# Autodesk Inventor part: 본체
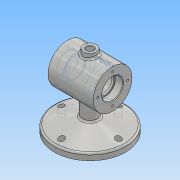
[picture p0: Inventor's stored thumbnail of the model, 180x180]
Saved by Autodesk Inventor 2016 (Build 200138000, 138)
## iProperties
Created: 2018-12
Part Number: 본체
Material: 알루미늄 6061
Document SubType Name: Modeling
Designer: Administrator
Density: 2.7 g/cm^3
Appearance: 알루미늄 - 평지
Author: Administrator
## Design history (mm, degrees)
sketch "스케치2"
  geometry: L1 (0, 0)-(70, 0); L2 (70, 0)-(70, 30); L3 (70, 30)-(0, 30); L4 (0, 30)-(0, 0); L5 (0, 16)-(12, 16); L6 (12, 16)-(12, 14); L7 (12, 14)-(15, 14); L8 (15, 14)-(15, 25); L9 (15, 25)-(55, 25); L10 (55, 25)-(55, 14); L11 (55, 14)-(58, 14); L12 (58, 14)-(58, 16); L13 (58, 16)-(70, 16)
  constraints: 26 end point, 7 perpendicular, 6 point on line, 2 horizontal, 2 parallel
  dimensions: "d0" = 70 distance between parallel lines of L2 L4; "d1" = 32 diameter of L5 L1; "d2" = 28 diameter of L7 L1; "d3" = 3 distance between parallel lines of L6 L8; "d4" = 50 diameter of L9 L1; "d5" = 3 distance between parallel lines of L12 L10; "d6" = 60 diameter of L3 L1; "d13" = 40 distance between parallel lines of L10 L8; "d14" = 12 distance between parallel lines of L4 L6
revolve "회전1" sketch "스케치2" stored, may be unused: angle "d7" = 90 deg
fillet "모깎기1" dims "d8" = 3
fillet "모깎기2" dims "d9" = 0.3
chamfer "모따기1" distance "d10" = 1; stored, may be unused: second distance "d11" = 2, angle "d12" = 45 deg
node "작업 평면1"
sketch "스케치3"
  geometry: L1 (0, -30)-(0, 30) reference; L2 (0, 30)-(70, 30) reference; L3 (0, -30)-(70, -30) reference; L4 (35, 30)-(35, -30); C1 r 10 at (35, 0); 2 further points
  constraints: 3 midpoint, 2 end point, 1 centre point, 1 coincident
  dimensions: "d16" = 20 diameter of C1; "d19" = 35 distance between parallel lines of L1 L4 (derived)
extrude "돌출1" join sketch "스케치3" stored distance "d20" = 7; taper "d21" = 0 deg
hole "구멍1" diameter "d24" = 10; stored, may be unused: countersink angle "d28" = 90 deg, drill point angle "d30" = 0 deg; dims "d22" = 10, "d23" = 10, "d25" = 6, "d26" = 4, "d27" = 2, "d29" = 8
chamfer "모따기2" distance "d31" = 1; stored, may be unused: second distance "d32" = 2, angle "d33" = 45 deg
sketch "스케치4" dims "d34" = 46
  geometry: L1 (0, 0)-(-30, 0); 3 further points
  constraints: 2 end point, 2 horizontal alignment, 1 coincident, 1 horizontal, 1 point on line, 3 other
hole "구멍2" sketch "스케치4" at (-23, 0) diameter "d35" = 3.242; stored, may be unused: countersink angle "d39" = 90 deg, drill point angle "d41" = 118 deg; dims "d36" = 8, "d37" = 12.24, "d38" = 3.58, "d40" = 10
node "작업 평면2"
fillet "모깎기3" dims "d46" = 3
node "작업 평면3"
sketch "스케치5"
  geometry: L1 (52, 25)-(52, -25) reference; L2 (18, -25)-(18, 25) reference; C1 r 55 at (35, 0); 3 further points
  constraints: 1 centre point, 1 vertical alignment, 2 other
  dimensions: "d48" = 110 diameter of C1
extrude "돌출2" join sketch "스케치5" distance "d49" = 10; taper "d50" = 0 deg
sketch "스케치6" dims "d51" = 88
  geometry: L1 (0, 0)-(0, -44); C1 r 55 at (0, 0) reference; C2 r 44 at (0, 0); 1 further point
  constraints: 2 coincident, 2 end point, 1 centre point, 1 vertical, 1 vertical alignment, 3 other
extrude "돌출3" join sketch "스케치6" distance "d52" = 11; taper "d53" = -75 deg
sketch "스케치8"
  geometry: C1 r 13.947 at (0, 0) reference; C2 r 12 at (0, 0); 1 further point
  constraints: 1 centre point, 1 coincident
  dimensions: "d58" = 24 diameter of C2
extrude "돌출4" join sketch "스케치8" stored distance "d59" = 1; taper "d60" = 0 deg
fillet "모깎기4" dims "d61" = 3
fillet "모깎기5" dims "d62" = 3
sketch "스케치10" dims "d63" = 88
  geometry: L1 (0, 0)-(0, -44); C1 r 55 at (0, 0) reference; 2 further points
  constraints: 2 coincident, 2 end point, 1 vertical, 1 vertical alignment, 2 other
hole "구멍3" sketch "스케치10" at (0, -44) diameter "d64" = 9; stored, may be unused: countersink angle "d68" = 90 deg, drill point angle "d70" = 0 deg; dims "d65" = 8, "d66" = 14, "d67" = 14, "d69" = 10
node "작업 평면4"
sketch "스케치11"
  geometry: L1 (0, 30)-(-70, 30) reference; L2 (-70, 30)-(-70, -30) reference; 2 further points
  constraints: 1 other
  dimensions: "d75" = 35 distance from line of L2 point (-35, 0); "d76" = 30 distance from line of L1 point (-35, 0)
feature "엠보싱1" sketch "스케치11" dims "d0" = 70, "d1" = 32, "d2" = 28, "d3" = 3, "d4" = 50, "d5" = 3, "d6" = 60, "d13" = 40, "d14" = 12, "d77" = 0.5, "d78" = 0
node "솔리드1"
pattern_circular "원형 패턴1" dims angle "d43" = 360 deg
mirror "대칭1"
pattern_circular "원형 패턴2" dims angle "d72" = 360 deg
node "투영된 루프1"
node "절단 모서리 투영1"
node "절단 모서리 투영3"
other parameters: "d15" = 37, "d45" = 35, "d47" = -75, "d74" = 30.75
